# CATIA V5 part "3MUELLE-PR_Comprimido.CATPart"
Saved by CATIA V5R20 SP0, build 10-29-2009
Part number: 3MUELLE-PR_Comprimido
Revision: ANY
Definition: UNKNOWN
Nomenclature: 3MUELLE-PR_Comprimido
Source: Unknown
Bounding box of the stored display mesh (mm): x -4.6 to 4.6, y 0.512 to 17.5, z -4.6 to 4.6
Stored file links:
  C:\Users\Utente\Desktop\IO LAVORO\3D X SITO CF\CUMSA\3D files PR.233230\PR 263230\3MUELLE-PR_Comprimido.CATPart
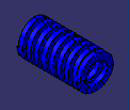
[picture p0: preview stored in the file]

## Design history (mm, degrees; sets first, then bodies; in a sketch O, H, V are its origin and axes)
Body1 "Cortar-Extruir1" (main body)
  Solid1: solid without history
